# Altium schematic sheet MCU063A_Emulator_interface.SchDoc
size 431 x 279 mm; Date: Not shown in title block; ApprovedBy: Not shown in title block; CheckedBy: Not shown in title block; Author: Not shown in title block; CompanyName: Not shown in title block; DrawnBy: Cody Watkins; Engineer: Not shown in title block; Organization: Not shown in title block; Address1: Not shown in title block; Address2: Not shown in title block; Address3: Not shown in title block; Address4: Not shown in title block; DocumentNumber: 10; Revision: Use project parameter SCH_Rev; SheetNumber: 10; SheetTotal: 11; PageSetup: Record=PageOptions¦CenterHorizontal=True¦CenterVertical=True¦PrintScale=1.00¦XCorrection=1.00¦YCorrection=1.00¦PrintKind=0¦BorderSize=5000000¦LeftOffset=0¦BottomOffset=0¦Orientation=2¦PaperLength=1000¦PaperWidth=1000¦Scale=100¦PaperSource=15¦PrintQuality=600¦MediaType=1¦DitherType=10¦PaperKind=Letter¦PrintScaleMode=1
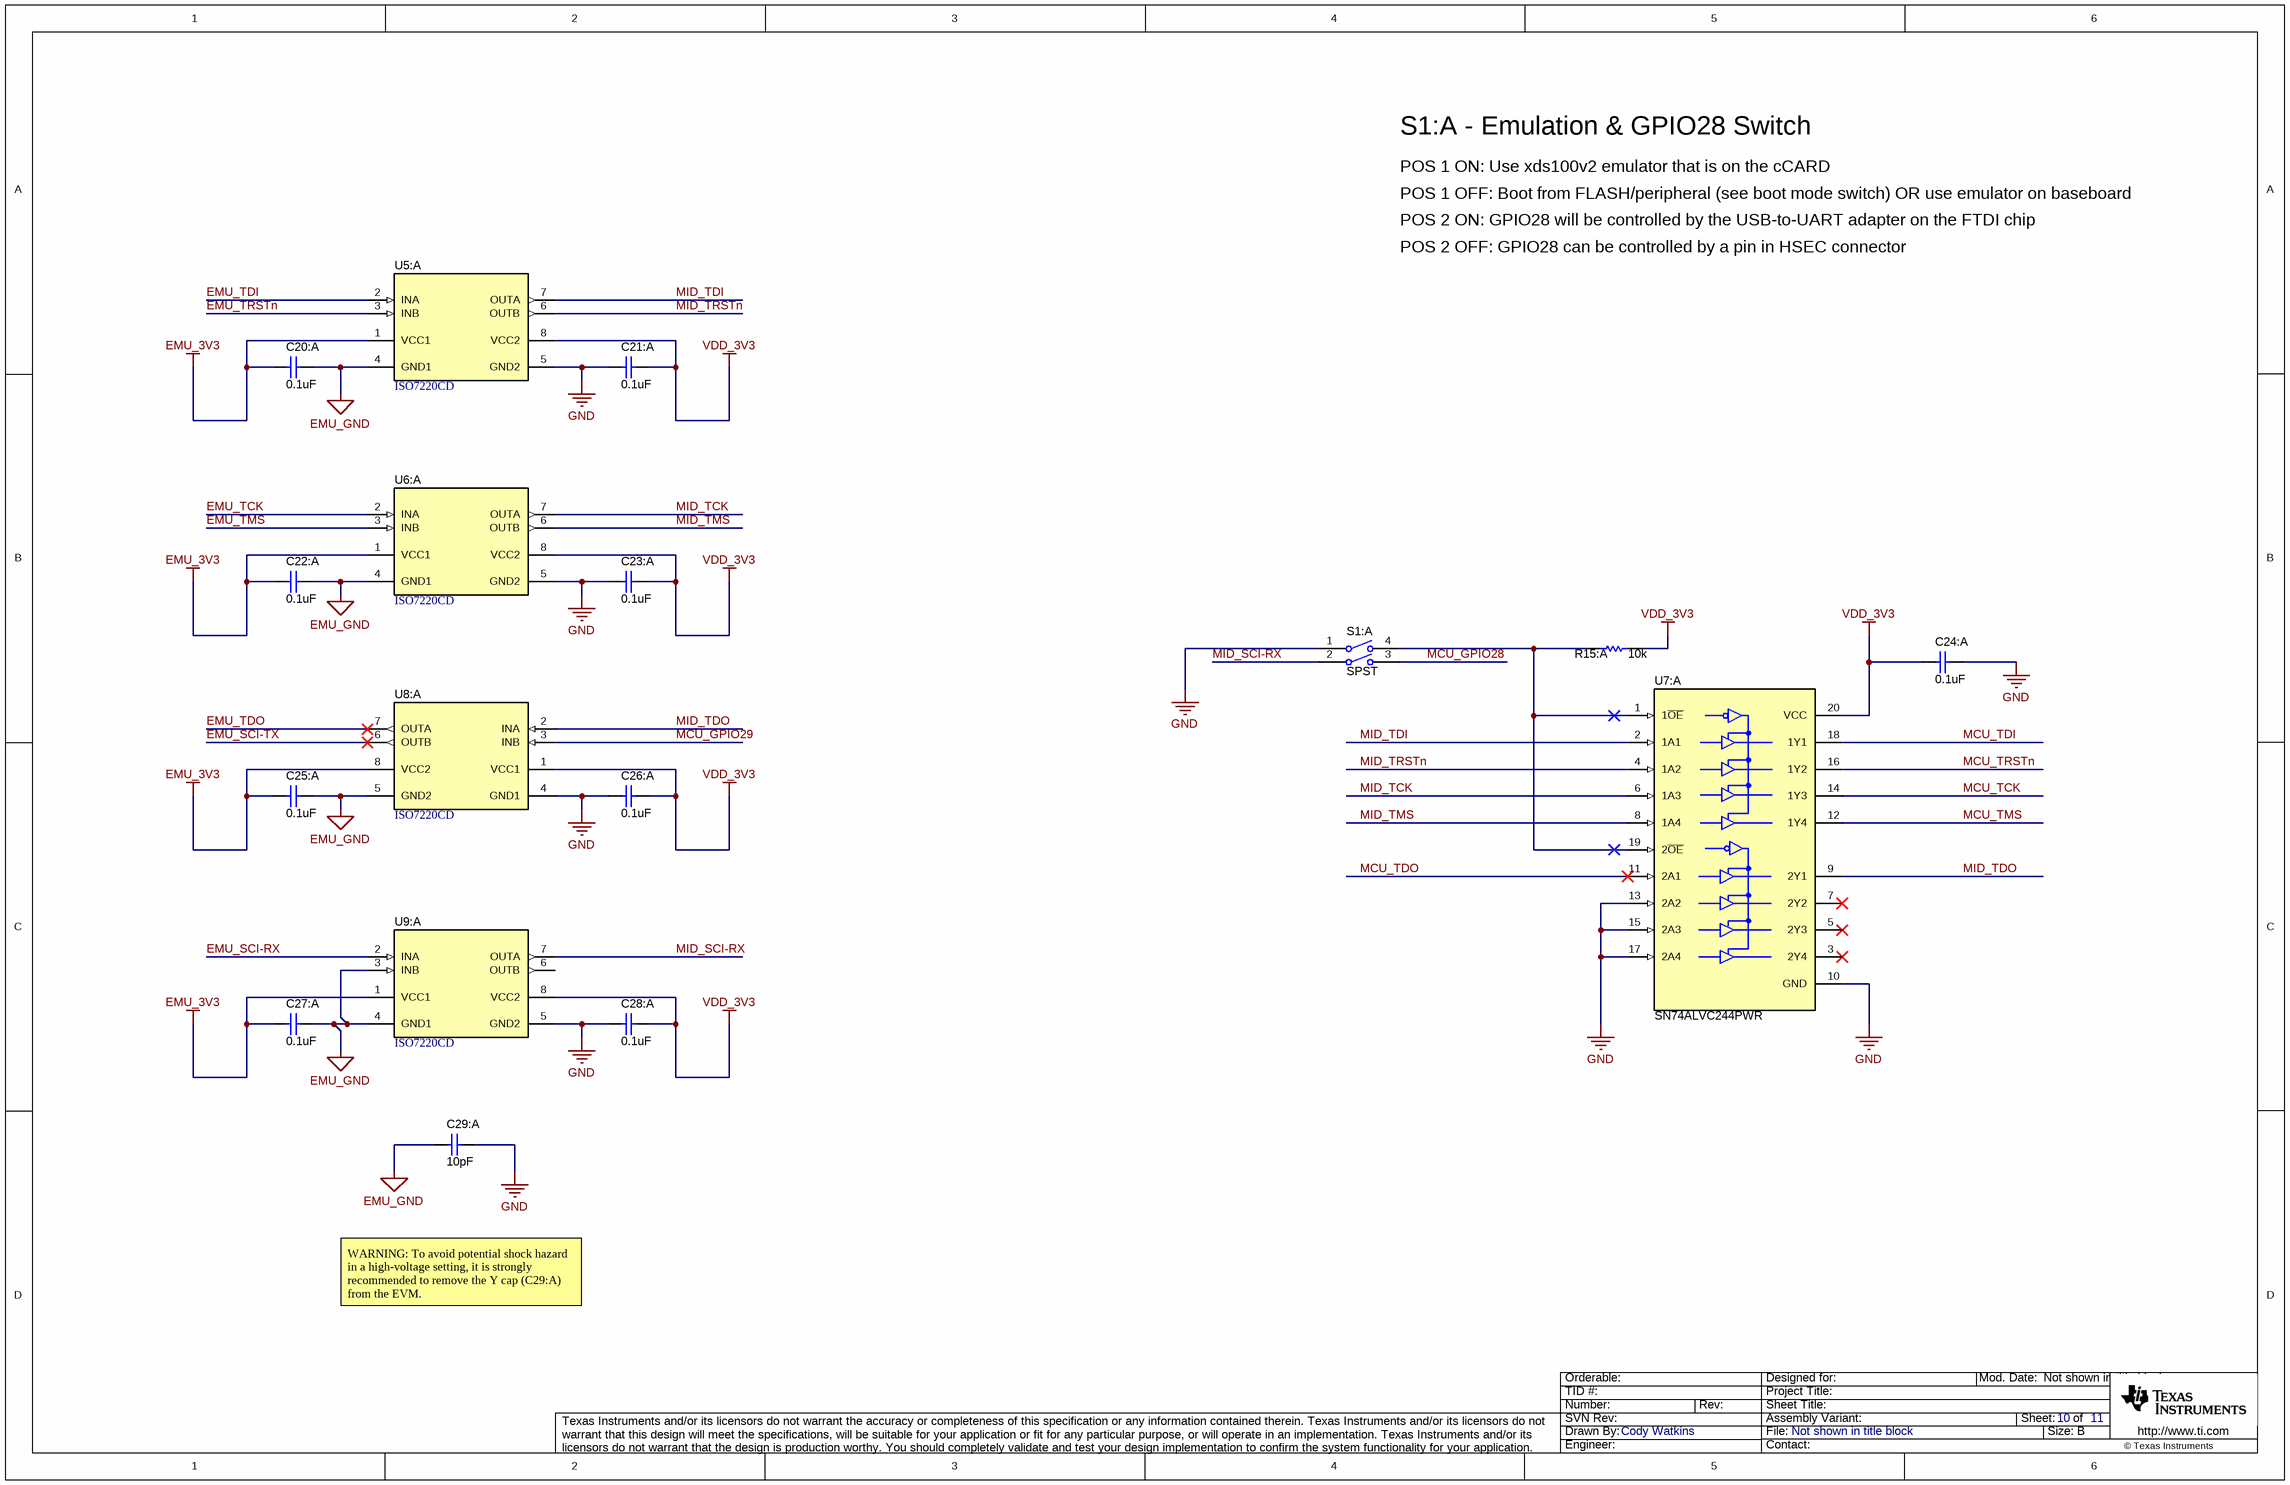
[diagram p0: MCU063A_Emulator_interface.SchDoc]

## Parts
C20:A  ValueDisplayed: 0.1uF  [0402]  (hidden comment: CL05B104KP5NNNC)
C21:A  ValueDisplayed: 0.1uF  [0402]  (hidden comment: CL05B104KP5NNNC)
C22:A  ValueDisplayed: 0.1uF  [0402]  (hidden comment: CL05B104KP5NNNC)
C23:A  ValueDisplayed: 0.1uF  [0402]  (hidden comment: CL05B104KP5NNNC)
C24:A  ValueDisplayed: 0.1uF  [0402]  (hidden comment: CL05B104KP5NNNC)
C25:A  ValueDisplayed: 0.1uF  [0402]  (hidden comment: CL05B104KP5NNNC)
C26:A  ValueDisplayed: 0.1uF  [0402]  (hidden comment: CL05B104KP5NNNC)
C27:A  ValueDisplayed: 0.1uF  [0402]  (hidden comment: CL05B104KP5NNNC)
C28:A  ValueDisplayed: 0.1uF  [0402]  (hidden comment: CL05B104KP5NNNC)
C29:A  ValueDisplayed: 10pF  [1812_180]  (hidden comment: C1812C100JHGACTU)
R15:A  ValueDisplayed: 10k  [0402]  (hidden comment: CRCW040210K0JNED)
S1:A  Circuit: SPST  [SW_218-2LP]  (hidden comment: 218-2LPST)
U5:A  ISO7220CD  [D0008B_N]
U6:A  ISO7220CD  [D0008B_N]
U7:A  SN74ALVC244PWR  [PW0020A_N]
U8:A  ISO7220CD  [D0008B_N]
U9:A  ISO7220CD  [D0008B_N]

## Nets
EMU_3V3: C20:A.2 C22:A.2 C25:A.2 C27:A.2 U5:A.1(VCC1) U6:A.1(VCC1) U8:A.8(VCC2) U9:A.1(VCC1)
EMU_GND: C20:A.1 C22:A.1 C25:A.1 C27:A.1 C29:A.2 U5:A.4(GND1) U6:A.4(GND1) U8:A.5(GND2) U9:A.3(INB) U9:A.4(GND1)
GND: C21:A.2 C23:A.2 C24:A.1 C26:A.2 C28:A.2 C29:A.1 S1:A.1 U5:A.5(GND2) U6:A.5(GND2) U7:A.10(GND) U7:A.13(2A2) U7:A.15(2A3) U7:A.17(2A4) U8:A.4(GND1) U9:A.5(GND2)
VDD_3V3: C21:A.1 C23:A.1 C24:A.2 C26:A.1 C28:A.1 R15:A.2 U5:A.8(VCC2) U6:A.8(VCC2) U7:A.20(VCC) U8:A.1(VCC1) U9:A.8(VCC2)
EMU_SCI-RX: U9:A.2(INA)
EMU_SCI-TX: U8:A.6(OUTB)
EMU_TCK: U6:A.2(INA)
EMU_TDI: U5:A.2(INA)
EMU_TDO: U8:A.7(OUTA)
EMU_TMS: U6:A.3(INB)
EMU_TRSTn: U5:A.3(INB)
MCU_GPIO28: S1:A.3
MCU_GPIO29: U8:A.3(INB)
MCU_TCK: U7:A.14(1Y3)
MCU_TDI: U7:A.18(1Y1)
MCU_TDO: U7:A.11(2A1)
MCU_TMS: U7:A.12(1Y4)
MCU_TRSTn: U7:A.16(1Y2)
MID_SCI-RX: S1:A.2 U9:A.7(OUTA)
MID_TCK: U6:A.7(OUTA) U7:A.6(1A3)
MID_TDI: U5:A.7(OUTA) U7:A.2(1A1)
MID_TDO: U7:A.9(2Y1) U8:A.2(INA)
MID_TMS: U6:A.6(OUTB) U7:A.8(1A4)
MID_TRSTn: U5:A.6(OUTB) U7:A.4(1A2)
NetR15:A_1: R15:A.1 S1:A.4 U7:A.1(1~{OE}) U7:A.19(2~{OE})

Not connected (* = marked no-connect by the designer): U7:A 3(2Y4)* 5(2Y3)* 7(2Y2)*; U9:A 6(OUTB)

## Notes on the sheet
- S1:A - Emulation & GPIO28 Switch
- POS 1 ON: Use xds100v2 emulator that is on the cCARD
- POS 1 OFF: Boot from FLASH/peripheral (see boot mode switch) OR use emulator on baseboard
- POS 2 ON: GPIO28 will be controlled by the USB-to-UART adapter on the FTDI chip
- POS 2 OFF: GPIO28 can be controlled by a pin in HSEC connector
- WARNING: To avoid potential shock hazard in a high-voltage setting, it is strongly recommended to remove the Y cap (C29:A) from the EVM.

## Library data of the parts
C20:A C21:A C22:A C23:A C24:A C25:A C26:A C27:A C28:A = CMP-0006343-2: CAP, CERM, 0.1 uF, 10 V, +/- 10%, X7R, 0402; Manufacturer: Samsung Electro-Mechanics; Polarized: N; Value: 0.1uF; U/M: EA; Cap_F: 100nF; Value1: Unknown; VDC_V: 10V; TaMin_C: -55°C; TaMax_C: 125°C; AEC Category: Q200; SizeArea_mm2: 0.5; SizeAreaWB_mm2: 3; SizeX_mm: 1; SizeZ_mm: 0.6
C29:A = CMP-0082066-1: CAP, CERM, 10 pF, 3000 V,+/- 5%, C0G/NP0, AEC-Q200 Grade 1, 1812; Manufacturer: Kemet; SizeAreaWB_mm2: 23.1; SizeArea_mm2: 14.4; AEC Qualified: Y; AEC Category: Q200; Value: 10pF; TaMax_C: 125°C; SizeZ_mm: 1.8; AEC Grade: 1; Polarized: N; TaMin_C: -55°C; SizeY_mm: 3.2; Value2: 3000V; U/M: EA; SizeX_mm: 4.5; Cap_Case: 1812
R15:A = CMP-0026825-5: RES, 10 k, 5%, 0.063 W, AEC-Q200 Grade 0, 0402; Manufacturer: Vishay-Dale; Value: 10k; Value_Code: 10k0; Power_W: 63mW; Value2: 0.063W; VDC_V: 50V; TempCo: 200 ppm/C; EIA_Code: E24; AEC Category: Q200; AEC Qualified: Y; AEC Grade: 0; SizeArea_mm2: 0.5; SizeX_mm: 1; SizeZ_mm: 0.6
S1:A = CMP-0002230-1: Switch, SPST, 2 Pos, 25mA, 24VDC, SMD; Manufacturer: CTS Electrocomponents; VDC_V: 24V; SwitchFunction: Off-On; PositionCount: 2; CurrentRating_mA: 25A
U5:A U6:A U8:A U9:A = CMP-0029375-1: 25 Mbps Dual Channels, 2 / 0, Digital Isolator, 3.3 V / 5 V, -40 to +125 degC, 8-pin SOIC (D), Green (RoHS & no Sb/Br); Manufacturer: Texas Instruments; Datarate(Mbps): 25; Input Noise Filter: Yes; Insulation Rating(VRMS): 2500; Prop Delay(Max)(ns): 42; Rating: Catalog; Supply Voltage(s)(V): 3.3, 5; TTL/CMOS Input Threshold: TTL
U7:A = CMP-0047070-3: Octal Buffer/Driver With 3-State OUtputs, PW0020A (TSSOP-20); Manufacturer: Texas Instruments; Bits(#): 8; F @ Nom Voltage(Max)(Mhz): 100; ICC @ Nom Voltage(Max)(mA): 0.024; Input Type: LVTTL; Rating: Catalog; tpd @ Nom Voltage(Max)(ns): 4.4,3.1,2.8; VCC(Max)(V): 3.6; VCC(Min)(V): 1.65; Voltage(Nom)(V): 1.8,2.5,2.7,3.3; AEC Category: Q200; AEC Qualified: N; CompType: IC; SizeArea_mm2: 43.56; SizeAreaWB_mm2: 73.96; SizeX_mm: 6.6; SizeZ_mm: 1.2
